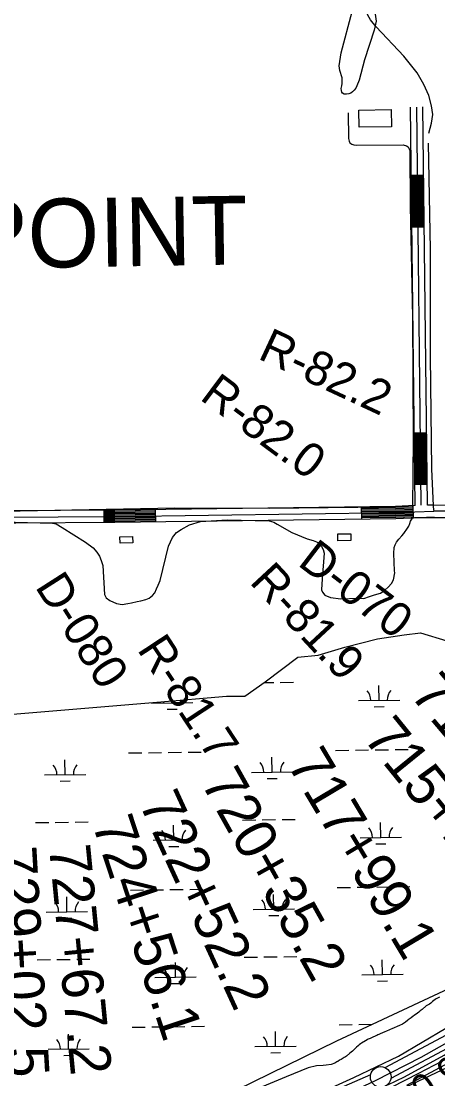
# Model space of a CAD drawing. Extents: x 3715084 to 3753216, y 488173 to 513963.
# Drawn here: x 3730139 to 3731150, y 501517 to 504083 of the extents above; entities that cross this region are included whole.
import ezdxf

# ---------------------------------------------------------------- set-up
doc = ezdxf.new("R2010")
doc.units = 0
for name, color, linetype in [('V-BLDG-OTLN', 7, 'Continuous'), ('V-FLOD-BASE', 7, 'Continuous'), ('V-LEVE-TOET', 7, 'Continuous'), ('V-RIVR-RANG', 7, 'Continuous'), ('V-RIVR-RANG-IDEN', 7, 'Continuous'), ('V-ROAD-CNTR', 7, 'Continuous'), ('V-RRAP-FSHR', 7, 'Continuous'), ('V-SITE-VEGE', 7, 'Continuous'), ('V-SURV-IDEN', 7, 'Continuous'), ('V-SURV-LINE', 7, 'Continuous'), ('V-TOPO-GNAM-IDEN', 7, 'Continuous'), ('V-TOPO-SHOR', 7, 'Continuous'), ('V-WETL-SWMP', 7, 'Continuous')]:
    doc.layers.add(name, color=color, linetype=linetype)

msp = doc.modelspace()

# ---------------------------------------------------------------- linework, layer by layer
at = {"layer": 'V-BLDG-OTLN'}
for points in [[(3731036.6, 503868.2), (3731037.2, 503826.6), (3730958.9, 503825.3), (3730958.2, 503866.9)], [(3730378.5, 502832), (3730409.6, 502833), (3730410.1, 502817.5), (3730379, 502816.4)], [(3730906.9, 502838.9), (3730938.7, 502839.3), (3730938.9, 502822.7), (3730907.2, 502822.3)]]:
    msp.add_lwpolyline(points, close=True, dxfattribs=at)
at = {"layer": 'V-FLOD-BASE'}
msp.add_lwpolyline([(3730083, 501275.3), (3730197, 501285.4), (3730287.6, 501296.6), (3730390.9, 501314), (3730500.5, 501337.1), (3730569.4, 501352.9), (3730639, 501373.1), (3730719.7, 501399.8), (3730830.6, 501440.2), (3730917.8, 501475.1), (3730998.5, 501513.4), (3731109.2, 501570), (3731216.8, 501630.2), (3731293.6, 501679.1), (3731346.7, 501713.7), (3731412.8, 501760.2), (3731484.4, 501811.6), (3731547.1, 501862.4), (3731607.1, 501917.2), (3731657.7, 501965.7)], dxfattribs=at)
at = {"layer": 'V-LEVE-TOET'}
for points in [[(3730125.3, 501317), (3730234, 501326.9), (3730374.7, 501344.5), (3730464.4, 501361.1), (3730554.6, 501382.1), (3730655.7, 501411.8), (3730764.1, 501446), (3730866.3, 501484.1), (3730945.8, 501520.4), (3731054, 501572.1), (3731169.1, 501640), (3731252.7, 501691.2), (3731313.4, 501729.4), (3731350.8, 501757.1), (3731389.1, 501783.2), (3731478.3, 501850.2), (3731556.7, 501917.3), (3731574.2, 501934.1), (3731603.4, 501964.1), (3731648.4, 502009.3)], [(3731028.1, 501502.6), (3731069, 501521.7), (3731165.1, 501574.5), (3731241, 501619), (3731307, 501661), (3731406.2, 501729.2), (3731496.3, 501794.2), (3731584.9, 501866.6), (3731654.1, 501929.4)]]:
    msp.add_lwpolyline(points, dxfattribs=at)
at = {"layer": 'V-ROAD-CNTR'}
for p, q in [((3731085.4, 503708.9), (3731115.4, 503709.2)), ((3731086.8, 503583.9), (3731116.8, 503584.2)), ((3731092.5, 503083.9), (3731122.5, 503084.3)), ((3731094, 502958.9), (3731124, 502959.3)), ((3730340.4, 502866.2), (3730340.2, 502896.2)), ((3730465.5, 502867.8), (3730465.1, 502897.8)), ((3730965.4, 502874.6), (3730965, 502904.6)), ((3731090.7, 502877.3), (3731089.6, 502907.3))]:
    msp.add_line(p, q, dxfattribs=at)
for points in [[(3731140.1, 502909.1), (3731460.2, 502909.4), (3731837.7, 502913.8), (3732083.1, 502919.7), (3732173.7, 502926.4), (3732193.3, 502930.5), (3732211.1, 502937.1), (3732216.7, 502941.9), (3732231.2, 502972.7), (3732245.4, 503020.3), (3732258.6, 503056.9), (3732270.9, 503094.6), (3732283.5, 503135.8), (3732296.3, 503191.6), (3732311.8, 503265.4), (3732320.9, 503314.1), (3732327.1, 503365.6), (3732337, 503409.7), (3732344.9, 503460.2), (3732365, 503636.2), (3732419.7, 504037.6), (3732449.2, 504271.2)], [(3732464.1, 504269.6), (3732434.6, 504035.7), (3732379.9, 503634.4), (3732359.8, 503458.2), (3732351.7, 503406.9), (3732341.9, 503363.1), (3732335.7, 503311.8), (3732326.5, 503262.5), (3732310.9, 503188.4), (3732298, 503131.9), (3732285.2, 503090), (3732272.8, 503052), (3732259.7, 503015.6), (3732245.3, 502967.3), (3732228.9, 502932.6), (3732218.9, 502924), (3732197.4, 502916.1), (3732175.8, 502911.6), (3732083.8, 502904.7), (3731837.9, 502898.8), (3731460.3, 502894.4), (3731140.2, 502894.1)], [(3731140.2, 502879.1), (3731460.4, 502879.4), (3731838.2, 502883.8), (3732084.6, 502889.8), (3732177.9, 502896.7), (3732201.6, 502901.6), (3732226.6, 502910.8), (3732241.1, 502923.3), (3732259.3, 502961.9), (3732274, 503011), (3732287, 503047.2), (3732299.5, 503085.5), (3732312.5, 503128), (3732325.6, 503185.2), (3732341.2, 503259.5), (3732350.6, 503309.5), (3732356.8, 503360.6), (3732366.5, 503404.1), (3732374.6, 503456.1), (3732394.8, 503632.5), (3732449.5, 504033.7), (3732479, 504268)], [(3731094.6, 502907.5), (3731083.5, 503874.2)], [(3731109.5, 502909.1), (3731098.5, 503874.4)], [(3731124.5, 502908.6), (3731113.5, 503874.6)], [(3731089.8, 503583.9), (3731088.4, 503708.9)], [(3731092.8, 503584), (3731091.4, 503709)], [(3731095.8, 503584), (3731094.4, 503709)], [(3731098.8, 503584), (3731097.4, 503709)], [(3731101.8, 503584.1), (3731100.4, 503709.1)], [(3731104.8, 503584.1), (3731103.4, 503709.1)], [(3731107.8, 503584.1), (3731106.4, 503709.1)], [(3731110.8, 503584.2), (3731109.4, 503709.2)], [(3731113.8, 503584.2), (3731112.4, 503709.2)], [(3731097, 502959), (3731095.5, 503084)], [(3731100, 502959), (3731098.5, 503084)], [(3731103, 502959), (3731101.5, 503084)], [(3731106, 502959.1), (3731104.5, 503084.1)], [(3731109, 502959.1), (3731107.5, 503084.1)], [(3731112, 502959.2), (3731110.5, 503084.1)], [(3731115, 502959.2), (3731113.5, 503084.2)], [(3731118, 502959.2), (3731116.5, 503084.2)], [(3731121, 502959.3), (3731119.5, 503084.2)], [(3728686.2, 502867.3), (3729405, 502875.5), (3730366.5, 502881.4), (3731047.5, 502890.7), (3731140.2, 502894.1)], [(3731094.6, 502907.5), (3731047.2, 502905.7), (3730366.3, 502896.4), (3729970.3, 502894)], [(3730465.1, 502894.8), (3730366.3, 502893.4), (3730340.2, 502893.2)], [(3731089.7, 502904.3), (3731047.2, 502902.7), (3730965.1, 502901.6)], [(3731089.9, 502901.3), (3731047.3, 502899.7), (3730965.1, 502898.6)], [(3731090, 502898.3), (3731047.4, 502896.7), (3730965.1, 502895.6)], [(3731090.1, 502895.3), (3731047.5, 502893.7), (3730965.2, 502892.6)], [(3731139.6, 502909.1), (3731124.5, 502908.6)], [(3731140.7, 502879.2), (3731047.9, 502875.7), (3730366.6, 502866.4), (3729405.1, 502860.5), (3728686.4, 502852.3)], [(3730465.2, 502891.8), (3730366.4, 502890.4), (3730340.2, 502890.2)], [(3730465.2, 502888.8), (3730366.4, 502887.4), (3730340.3, 502887.2)], [(3730465.2, 502885.8), (3730366.4, 502884.4), (3730340.3, 502884.2)], [(3730465.3, 502882.8), (3730366.5, 502881.4), (3730340.3, 502881.2)], [(3730465.3, 502879.8), (3730366.5, 502878.4), (3730340.3, 502878.2)], [(3730465.4, 502876.8), (3730366.5, 502875.4), (3730340.3, 502875.2)], [(3730465.4, 502873.8), (3730366.6, 502872.4), (3730340.3, 502872.2)], [(3730465.4, 502870.8), (3730366.6, 502869.4), (3730340.4, 502869.2)], [(3731090.2, 502892.3), (3731047.5, 502890.7), (3730965.2, 502889.6)], [(3731090.3, 502889.3), (3731047.6, 502887.7), (3730965.3, 502886.6)], [(3731090.4, 502886.3), (3731047.7, 502884.7), (3730965.3, 502883.6)], [(3731090.5, 502883.3), (3731047.8, 502881.7), (3730965.4, 502880.6)], [(3731090.6, 502880.3), (3731047.8, 502878.7), (3730965.4, 502877.6)]]:
    msp.add_lwpolyline(points, dxfattribs=at)
at = {"layer": 'V-RRAP-FSHR'}
msp.add_lwpolyline([(3731159, 501559.6), (3731103.2, 501530), (3731036.8, 501496)], dxfattribs=at)
at = {"layer": 'V-SITE-VEGE'}
for points in [[(3730993.4, 504128.3), (3731000.1, 504082.7), (3730995.3, 504061.1), (3730972, 503988.8), (3730958.8, 503939.5), (3730953.7, 503925.5), (3730950.8, 503919.8), (3730947.2, 503915), (3730942.9, 503910.9), (3730938.4, 503908.1), (3730933.9, 503906.1), (3730928.2, 503905.3), (3730922.9, 503905.9), (3730918.7, 503908.3), (3730916.7, 503910.8), (3730915.8, 503914.3), (3730915.7, 503919.7), (3730916.9, 503925.8), (3730917.7, 503931.7), (3730918, 503938.2), (3730917.6, 503945.4), (3730911.8, 503963.3), (3730910.4, 503974.4), (3730915.4, 504005.5), (3730942.4, 504106)], [(3730094.9, 502867.9), (3730215, 502865.2), (3730224.3, 502863.3), (3730239.1, 502854.7), (3730295, 502819), (3730313.8, 502804.9), (3730323.1, 502794.8), (3730329.2, 502785), (3730333.4, 502774.4), (3730337, 502762.2), (3730341.6, 502692.4), (3730345.1, 502683.8), (3730354, 502677.5), (3730370.2, 502669.8), (3730384, 502667.7), (3730398.2, 502669.8), (3730406.5, 502672), (3730420.7, 502674.8), (3730429.7, 502676.4), (3730441.9, 502679.8), (3730449.6, 502683.3), (3730457.9, 502689.7), (3730463.4, 502696.4), (3730467.7, 502705.5), (3730471.4, 502715), (3730476.3, 502725.8), (3730496.7, 502809.3), (3730506.2, 502830.6), (3730516.3, 502842.7), (3730527.1, 502849.8), (3730547.5, 502861.3), (3730574.1, 502869.1), (3730638.9, 502873.1), (3730740.9, 502870.7), (3730751.9, 502867.6), (3730760.2, 502862.7), (3730795.8, 502842.7), (3730833.1, 502827), (3730847.3, 502822.8), (3730855.8, 502819.4), (3730860.1, 502817.1), (3730863.1, 502814.1), (3730868, 502808.5), (3730871.6, 502801.4)], [(3730871.6, 502801.4), (3730874.2, 502791.9), (3730869.5, 502729.8), (3730867.8, 502703.6), (3730870, 502697.3), (3730875.9, 502690), (3730889.4, 502684.9), (3730914.4, 502681.1), (3730955.5, 502683.4), (3730970.5, 502682.1), (3730984.3, 502686.9), (3730996.5, 502690.9), (3731011, 502695.3), (3731022.4, 502703.6), (3731029.1, 502709.5), (3731037.4, 502718.6), (3731042.4, 502727.7), (3731045.5, 502744.3), (3731045, 502749.8), (3731042.7, 502791.6), (3731043.9, 502806.3), (3731046, 502812.8), (3731049.3, 502818.6), (3731055, 502825.9), (3731062.1, 502834), (3731067, 502840.1), (3731076.4, 502852.7), (3731079.5, 502857.7), (3731081.9, 502864), (3731083.6, 502869.5), (3731088.1, 502877.2), (3731093.6, 502878.4), (3731227.4, 502878.5)], [(3731153.5, 501715.5), (3731145.6, 501711.3), (3731143.2, 501709.8), (3731140.1, 501707), (3731137, 501704.8), (3731132.6, 501700.9), (3731129.3, 501698.7), (3731126.5, 501697.1), (3731124.6, 501696.1), (3731121.8, 501694.1), (3731111.6, 501685.6), (3731106.7, 501681.8), (3731103.3, 501678.9), (3731097.2, 501674.3), (3731095.5, 501673.1), (3731092.7, 501670.7), (3731090.2, 501669.2), (3731085.4, 501665.4), (3731082.5, 501663.4), (3731080.5, 501661.8), (3731078.2, 501660.4), (3731076, 501658.5), (3731071.1, 501654.5), (3731066.8, 501651.5), (3731064.4, 501650.1), (3731056.7, 501646.2), (3731038.6, 501638.6), (3731034.5, 501636.8), (3731030.8, 501635), (3731026.6, 501633.4), (3731024.9, 501632.5), (3731021.1, 501630.9), (3731010.3, 501626.5), (3731006.4, 501624.7), (3731004.6, 501623.7), (3731002.2, 501622.7), (3730999.7, 501621.9), (3730997.9, 501620.9), (3730992.4, 501618.5), (3730989, 501616.8), (3730985.9, 501615.4), (3730983.1, 501614), (3730981.2, 501613.2), (3730978.6, 501611.6), (3730974.1, 501609.4), (3730964.8, 501603.9), (3730962.1, 501601.9), (3730958.9, 501599.3), (3730956.6, 501597.1), (3730952.5, 501594), (3730946, 501587.6), (3730944.2, 501586.2), (3730942.6, 501584.5), (3730936.5, 501579.1), (3730928.5, 501572.6), (3730925.7, 501570.6), (3730923, 501568.8), (3730920, 501567.2), (3730915.5, 501564.5), (3730911, 501562.3), (3730906.9, 501559.5), (3730904.5, 501558.3), (3730902.5, 501557.1), (3730900, 501555.3), (3730891.1, 501551.7), (3730879.3, 501550.1), (3730871.4, 501549.7), (3730855.8, 501549.1), (3730835.4, 501543.7), (3730782, 501522.4), (3730704.7, 501489.8)], [(3731074.2, 501501.7), (3731179.1, 501557.7)]]:
    msp.add_lwpolyline(points, dxfattribs=at)
at = {"layer": 'V-SURV-LINE'}
for points in [[(3731021.8, 501544.4), (3731194.7, 501636.9)], [(3731208.8, 501610.4), (3731035.9, 501518)], [(3730824.8, 501456.5), (3730986.9, 501527.5)]]:
    msp.add_lwpolyline(points, dxfattribs=at)
msp.add_circle((3731011.2, 501521.8), 25, dxfattribs=at)
at = {"layer": 'V-TOPO-SHOR'}
for points in [[(3731000.4, 504069.2), (3730986.2, 504085.7), (3730980.2, 504097.5), (3730974.1, 504116.4), (3730971.2, 504143.9), (3730973.6, 504188.8), (3730978, 504260.3)], [(3731127.7, 503811.4), (3731134.6, 503835), (3731137.4, 503856.3), (3731134.8, 503877.6), (3731127.6, 503902.1), (3731115.5, 503929.1), (3731099.5, 503957.2), (3731067.4, 503998), (3731000.4, 504069.2)], [(3730932.4, 503860.5), (3730933, 503798.1), (3730934.4, 503791.6), (3730936.4, 503787.6), (3730941.6, 503784.1), (3730945.9, 503782.7), (3730953.2, 503782), (3731065.5, 503782.6), (3731073.4, 503780.6), (3731077.7, 503777.7), (3731079.5, 503774.7), (3731082.1, 503769.2), (3731082.6, 503633.9), (3731088.1, 503364.4), (3731090.1, 503067), (3731088, 502905.4)], [(3731126.3, 503786.9), (3731130.8, 503529.2), (3731131.5, 503270.4), (3731134.3, 502996.2), (3731138.8, 502907.6), (3731139.4, 502895.7)], [(3732061.2, 502926.4), (3731817, 502916.9), (3731550.5, 502913.2), (3731258.7, 502908.4), (3731138.8, 502907.6)], [(3729967.9, 502891.8), (3730220.7, 502896.6), (3730512.2, 502902.6), (3730741.2, 502901.3), (3731026.8, 502904.3), (3731088, 502905.4)]]:
    msp.add_lwpolyline(points, dxfattribs=at)
at = {"layer": 'V-WETL-SWMP'}
for p, q in [((3730728.2, 502478.3), (3730751.8, 502478.6)), ((3730767.8, 502478.8), (3730799.8, 502479.2)), ((3731007.2, 502435.3), (3731006.8, 502471.3)), ((3730505.3, 502429.1), (3730505.3, 502434)), ((3730957.2, 502434.7), (3731057.2, 502435.9)), ((3730455.3, 502428.4), (3730555.3, 502429.7)), ((3730493.5, 502413.5), (3730517.5, 502413.8)), ((3730995.4, 502419.7), (3731019.4, 502420)), ((3730400, 502307.7), (3730432, 502308.1)), ((3730448, 502308.3), (3730480, 502308.7)), ((3730496, 502308.9), (3730528, 502309.3)), ((3730544, 502309.5), (3730576, 502309.9)), ((3730901.9, 502313.9), (3730933.9, 502314.3)), ((3730949.9, 502314.5), (3730981.9, 502314.9)), ((3730997.9, 502315.1), (3731029.9, 502315.5)), ((3731045.9, 502315.7), (3731077.9, 502316.1)), ((3730246.1, 502255), (3730245.6, 502291)), ((3730747.9, 502261.3), (3730747.5, 502297.3)), ((3730196.1, 502254.4), (3730296.1, 502255.6)), ((3730697.9, 502260.6), (3730797.9, 502261.9)), ((3730234.2, 502239.4), (3730258.2, 502239.7)), ((3730736.1, 502245.7), (3730760.1, 502246)), ((3730174.1, 502138.6), (3730206.1, 502139)), ((3730222.1, 502139.2), (3730254.1, 502139.6)), ((3730270.1, 502139.8), (3730302.1, 502140.2)), ((3730509.5, 502096.4), (3730509, 502132.4)), ((3730676, 502144.9), (3730708, 502145.3)), ((3730724, 502145.5), (3730756, 502145.9)), ((3730772, 502146.1), (3730804, 502146.5)), ((3731011.4, 502102.7), (3731010.9, 502138.7)), ((3730961.4, 502102.1), (3731061.4, 502103.3)), ((3730459.5, 502095.8), (3730559.5, 502097)), ((3730497.7, 502080.8), (3730521.7, 502081.1)), ((3730999.6, 502087.1), (3731023.6, 502087.4)), ((3730404.2, 501975), (3730436.2, 501975.4)), ((3730452.2, 501975.6), (3730484.2, 501976)), ((3730500.2, 501976.2), (3730532.1, 501976.6)), ((3730548.1, 501976.8), (3730580.1, 501977.2)), ((3730906, 501981.3), (3730938, 501981.7)), ((3730954, 501981.9), (3730986, 501982.3)), ((3731002, 501982.5), (3731034, 501982.9)), ((3731050, 501983.1), (3731082, 501983.5)), ((3730250.2, 501922.3), (3730249.8, 501958.3)), ((3730752.1, 501928.6), (3730751.6, 501964.6)), ((3730200.2, 501921.7), (3730300.2, 501923)), ((3730702.1, 501928), (3730802.1, 501929.2)), ((3730238.4, 501906.8), (3730262.4, 501907.1)), ((3730740.3, 501913), (3730764.3, 501913.3)), ((3730178.3, 501806), (3730210.3, 501806.4)), ((3730226.2, 501806.6), (3730258.2, 501807)), ((3730274.2, 501807.2), (3730306.2, 501807.6)), ((3730513.7, 501763.8), (3730513.2, 501799.8)), ((3730680.1, 501812.3), (3730712.1, 501812.7)), ((3730728.1, 501812.9), (3730760.1, 501813.3)), ((3730776.1, 501813.5), (3730808.1, 501813.9)), ((3731015.5, 501770), (3731015.1, 501806)), ((3730965.5, 501769.4), (3731065.5, 501770.7)), ((3730463.7, 501763.1), (3730563.6, 501764.4)), ((3730501.8, 501748.2), (3730525.8, 501748.5)), ((3731003.7, 501754.4), (3731027.7, 501754.7)), ((3730408.3, 501642.4), (3730440.3, 501642.8)), ((3730456.3, 501643), (3730488.3, 501643.4)), ((3730504.3, 501643.6), (3730536.3, 501644)), ((3730552.3, 501644.2), (3730584.3, 501644.6)), ((3730910.2, 501648.6), (3730942.2, 501649)), ((3730958.2, 501649.2), (3730990.2, 501649.6)), ((3730254.4, 501589.7), (3730253.9, 501625.7)), ((3730756.2, 501596), (3730755.8, 501632)), ((3730204.4, 501589.1), (3730304.4, 501590.3)), ((3730706.2, 501595.3), (3730806.2, 501596.6)), ((3730242.6, 501574.1), (3730266.6, 501574.4)), ((3730744.4, 501580.4), (3730768.4, 501580.7))]:
    msp.add_line(p, q, dxfattribs=at)
for points in [[(3732459.3, 504480.8), (3732424.6, 503990.6), (3732325.6, 503411.2), (3732300.8, 503223), (3732251.3, 503079.4), (3732157.2, 502856.6), (3732073, 502688.2), (3732038.4, 502584.2), (3731914.6, 502376.3), (3731716.5, 502133.6), (3731459, 501930.6), (3731201.5, 501747.4), (3730904.4, 501608.7), (3730661.7, 501489.9), (3730305.2, 501415.6), (3729938.8, 501395.8)], [(3729933.8, 502386.2), (3730468.6, 502430.7), (3730637, 502445.6), (3730681.6, 502445.6), (3730731.1, 502480.2), (3730810.3, 502539.7), (3730859.8, 502544.6), (3730924.2, 502564.4), (3731003.4, 502584.2), (3731067.8, 502594.1), (3731107.4, 502599.1), (3731171.8, 502579.3)], [(3731045.6, 501485), (3731217.2, 501565.7), (3731429.2, 501720.5), (3731530.1, 501764.2), (3731600.7, 501767.6), (3731631, 501760.8), (3731641.1, 501747.4), (3731637.8, 501730.6), (3731624.3, 501700.3), (3731610.8, 501676.7), (3731594, 501659.9), (3731550.3, 501622.9), (3731509.9, 501582.5), (3731486.4, 501552.2), (3731439.3, 501501.8)]]:
    msp.add_lwpolyline(points, dxfattribs=at)
for centre, start, end in [((3730952, 502435.1), 359.9442, 41.4878), ((3731062.4, 502436.5), 139.9442, 181.4878), ((3730450.1, 502428.8), 359.9442, 5.4589), ((3730560.6, 502430.2), 170.9349, 181.4878), ((3730190.8, 502254.8), 359.9442, 41.4878), ((3730301.3, 502256.2), 139.9442, 181.4878), ((3730692.7, 502261), 359.9442, 41.4878), ((3730803.2, 502262.4), 139.9442, 181.4878), ((3730956.1, 502102.5), 359.9442, 41.4878), ((3731066.6, 502103.8), 139.9442, 181.4878), ((3730454.2, 502096.2), 359.9442, 41.4878), ((3730564.7, 502097.6), 139.9442, 181.4878), ((3730195, 501922.1), 359.9442, 41.4878), ((3730305.4, 501923.5), 139.9442, 181.4878), ((3730696.8, 501928.4), 359.9442, 41.4878), ((3730807.3, 501929.8), 139.9442, 181.4878), ((3730960.3, 501769.8), 359.9442, 41.4878), ((3731070.8, 501771.2), 139.9442, 181.4878), ((3730458.4, 501763.5), 359.9442, 41.4878), ((3730568.9, 501764.9), 139.9442, 181.4878), ((3730199.1, 501589.5), 359.9442, 41.4878), ((3730309.6, 501590.9), 139.9442, 181.4878), ((3730701, 501595.7), 359.9442, 41.4878), ((3730811.5, 501597.1), 139.9442, 181.4878)]:
    msp.add_arc(centre, 35.2, start, end, dxfattribs=at)

# ---------------------------------------------------------------- texts
at = {"layer": 'V-RIVR-RANG'}
msp.add_text('10.9', height=67, rotation=33.2483, dxfattribs=at).set_placement((3731072.3, 501427.3))
at = {"layer": 'V-RIVR-RANG-IDEN'}
for s, rotation, p in [('R-82.2', 335.0271, (3730710.6, 503265.3)), ('R-82.0', 323.3233, (3730569.9, 503166.7)), ('D-070', 322.5693, (3730807.1, 502764.7)), ('R-81.9', 312.8957, (3730691, 502721.2)), ('D-080', 302.5683, (3730171.5, 502710.9)), ('R-81.7', 303.3885, (3730419.1, 502558.7))]:
    msp.add_text(s, height=83, rotation=rotation, dxfattribs=at).set_placement(p)
at = {"layer": 'V-SURV-IDEN'}
for s, rotation, p in [('713+51.7', 310.2635, (3731079.6, 502448.6)), ('715+12.3', 309.0218, (3730966.3, 502343.7)), ('717+99.1', 300.7953, (3730782.4, 502281.7)), ('720+35.2', 299.2454, (3730573.6, 502236.5)), ('722+52.2', 294.6986, (3730423.8, 502187)), ('724+56.1', 288.1985, (3730310.9, 502136.8)), ('729+02.5', 273.3334, (3730076.1, 502079.1)), ('727+67.2', 275.5069, (3730206.5, 502081.6))]:
    msp.add_text(s, height=100, rotation=rotation, dxfattribs=at).set_placement(p)
at = {"layer": 'V-TOPO-GNAM-IDEN'}
msp.add_text('POINT', height=167, rotation=0.918, dxfattribs=at).set_placement((3730007.2, 503481.8))

doc.saveas('drawing.dxf')
